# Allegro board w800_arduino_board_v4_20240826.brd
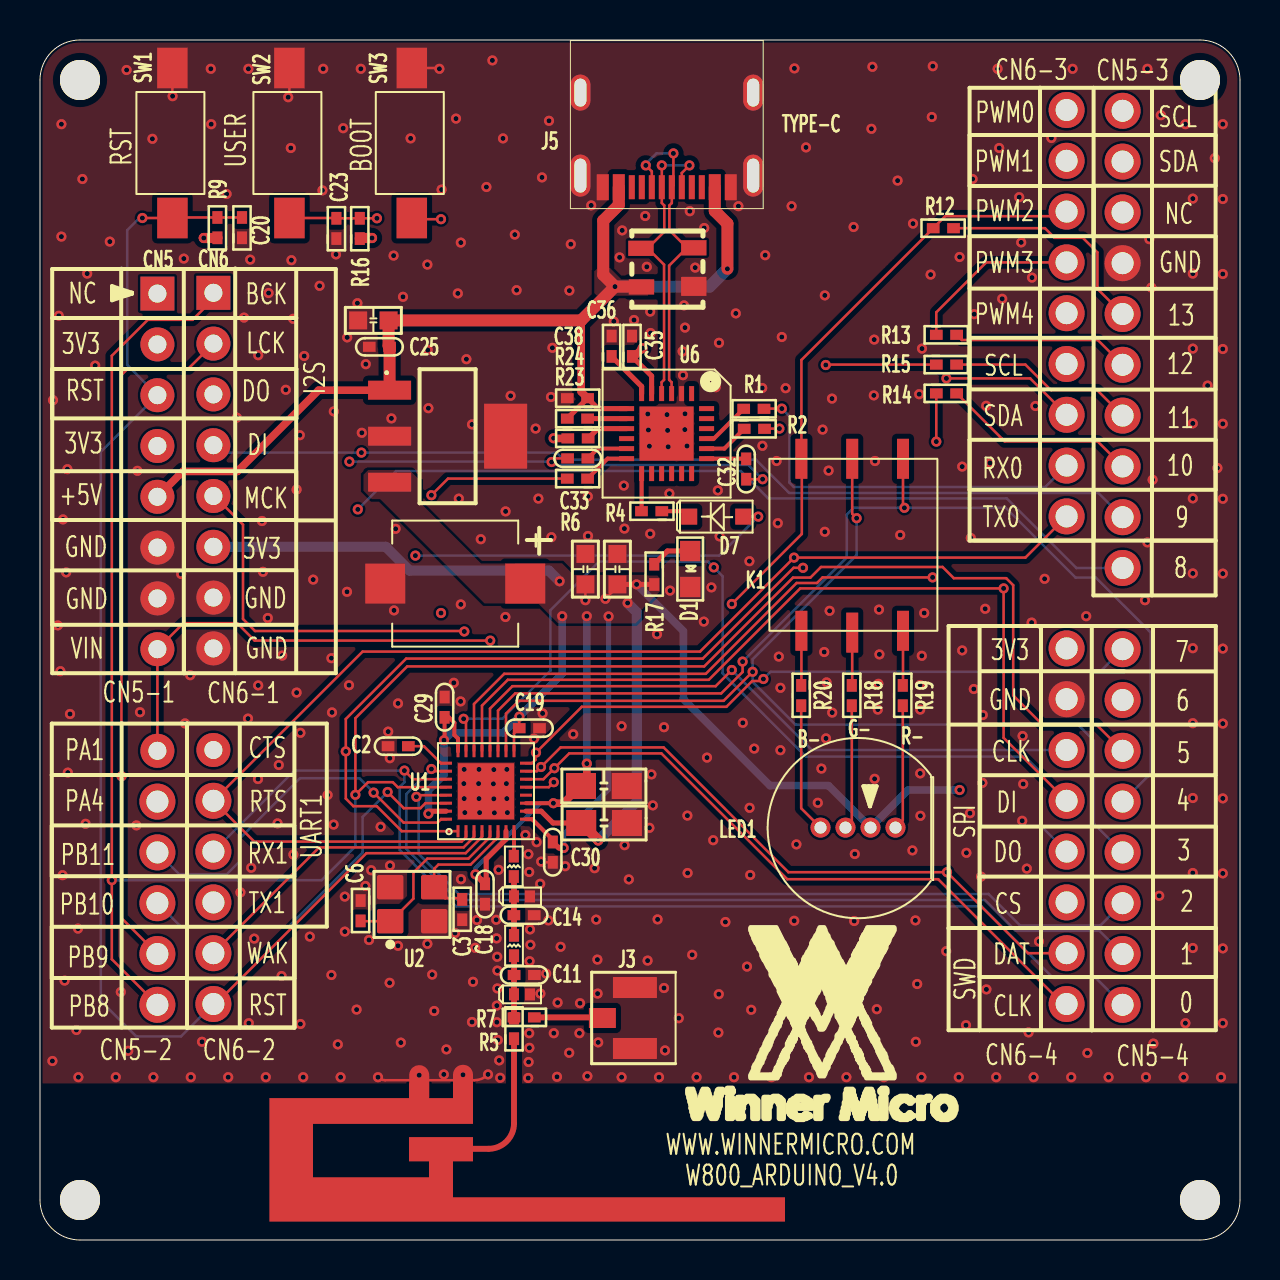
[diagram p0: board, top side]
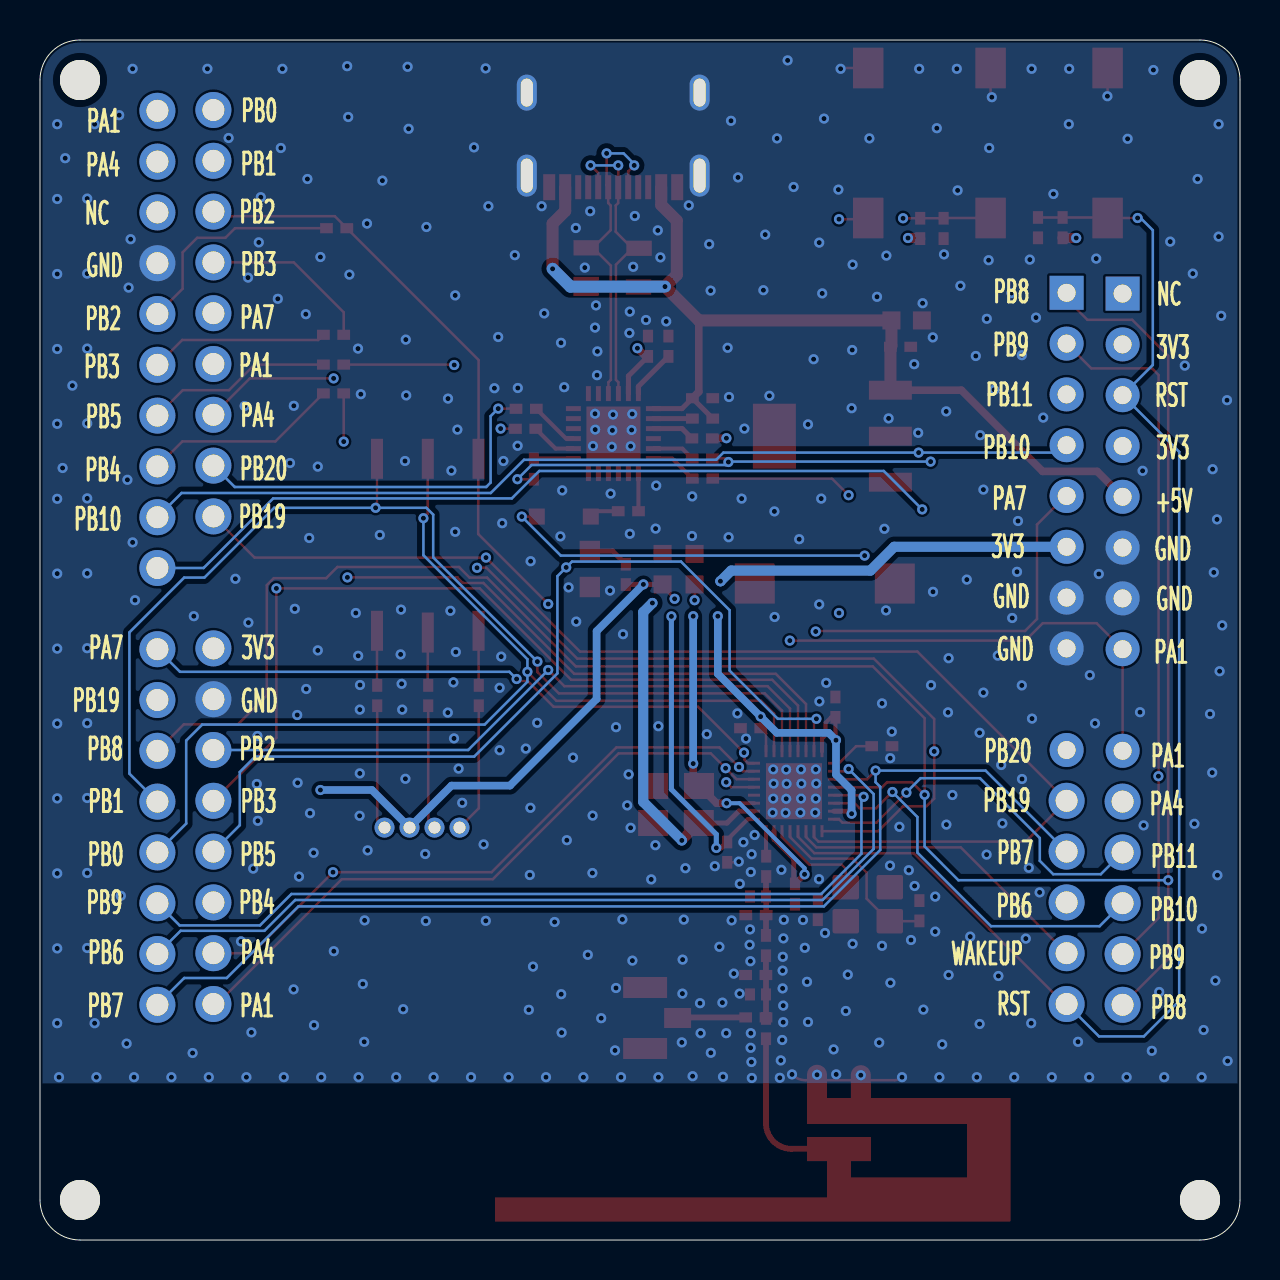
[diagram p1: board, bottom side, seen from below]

Outline 60 x 60 mm; copper layers: TOP, GND1, GND2, BOTTOM. Coordinates in mm from the lower left corner of the outline.
Outline path: 0,58 0,2 arc(0.59,0.59) 2,0 58,0 arc(59.41,0.59) 60,2 60,58 arc(59.41,59.41) 58,60 2,60 arc(0.59,59.41) 0,58

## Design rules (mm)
constraint set DEFAULT: min track width 0.127
net group D: nets DN DP

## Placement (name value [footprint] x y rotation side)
C2  4.7uF  [C0402]  18.42 24.69 180 top
C3  15pF  [R0402]  21.11 17.03 270 top
C6  15pF  [R0402]  16.03 16.97 270 top
C11  2pF  [C0402]  24.72 13.25 180 top
C14  1.5pF  [C0402]  24.71 16.24 180 top
C17  47uF  [C0805]  28.2 20.85 0 top
C18  1uF  [C0402]  22.25 17.81 270 top
C19  1uF  [C0402]  23.96 25.59 0 top
C20  1uF  [R0402]  10.1 50.11 90 top
C23  NC  [R0402]  14.82 50.07 90 top
C24  10uF  [C0603]  16.67 45.98 180 top
C25  1uF  [C0402]  17.48 44.66 180 top
C26  10uF  [C0603]  27.27 33.54 90 top
C27  10uF  [C0603]  28.87 33.54 90 top
C28  330uF  [CAPE-6DX13L]  20.76 32.82 180 top
C29  1uF  [C0402]  20.23 26.13 90 top
C30  10nF  [C0402]  25.64 19.9 270 top
C31  8.2pF  [L0402]  23.69 18.68 270 top
C32  4.7uF  [C0402]  35.31 38.04 90 top
C33  4.7uF  [C0402]  26.38 39.08 0 top
C35  1uF  [R0402]  29.6 44.18 90 top
C36  0.1uF  [R0402]  28.58 44.18 90 top
C38  1uF  [R0402]  27.38 42.09 180 top
C39  47uF  [C0805]  28.19 22.7 0 top
CN5  DIP8  [ARDUINO_HDRM2]  5.87 27 0 top
CN6  DIP8  [ARDUINO_HDRMDIP]  5.87 27.04 0 top
D1  LED  [LED0603]  32.51 33.55 270 top
D2  WM0310001  [TVS0402]  24.1 12.28 0 top
D3  WM0310001  [TVS0402]  24.1 17.18 0 top
D7  1N5819WS  [SOD-323]  32.46 36.17 0 top
J3  IPX  [TC35]  28.98 11.1 0 top
J4  ANT  [IFA_TI1]  24.36 4.38 180 top
J5  -  [TYPE-C]  31.34 59.97 180 top
K1  EM-03KP  [SWITCH3_2]  38.07 39.06 0 top
L2  1.5nH  [L0402]  23.7 14.72 270 top
LED1  8MM RGB LED  [RGB_LED]  40.9 20.62 180 top
NOREF  -  [unnamed]  2 58 0 top
NOREF#2  -  [unnamed]  58 2 0 top
NOREF#3  -  [unnamed]  58 58 0 top
NOREF#4  -  [unnamed]  2 2 0 top
R1  33R  [R0402]  36.2 41.56 180 top
R2  33R  [R0402]  35.21 40.56 0 top
R4  33R  [R0402]  31.09 36.44 180 top
R5  8.2pF  [R0402]  23.7 10.06 90 top
R6  33R  [R0402]  27.38 38.07 180 top
R7  NC  [R0402]  24.72 11.13 180 top
R9  10K  [R0402]  8.87 50.11 90 top
R12  33R  [R0402]  44.66 50.59 0 top
R13  33R  [R0402]  44.81 45.26 0 top
R14  33R  [R0402]  44.81 42.33 0 top
R15  33R  [R0402]  44.81 43.77 0 top
R16  10K  [R0402]  15.99 50.07 90 top
R17  1.5K  [R0402]  30.71 33.79 270 top
R18  100R  [R0402]  40.59 27.73 270 top
R19  100R  [R0402]  43.14 27.73 270 top
R20  100R  [R0402]  38.06 27.73 270 top
R23  NC  [R0402]  26.39 40.08 0 top
R24  0R  [R0402]  27.38 41.07 180 top
SW1  K2-1107ST-A4SW-06  [SW4]  6.62 51.1 90 top
SW2  K2-1107ST-A4SW-06  [SW4]  12.47 51.1 90 top
SW3  K2-1107ST-A4SW-06  [SW4]  18.59 51.1 90 top
U1  W800_32pin  [W800-QFN32]  22.3 22.44 90 top
U2  XTAL_40MHz  [OSCCC250X320X110]  18.8 16.93 90 top
U4  AP7361-33E-13  [SOT-223]  20.38 40.19 270 top
U6  CH342F  [QFN24_4MMX4MM]  31.33 40.32 270 top
U7  SP0503BAHTG  [SOT143_2]  31.37 48.54 90 top

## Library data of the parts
C2 C3 C6 C11 C14 C17-C20 C23-C27 C29 C30 C32 C33 C35 C36 C38 C39 = CAP NP
C28 = C_0: room: PWR
C31 L2 = INDUCTOR
CN5 = CON8_5
CN6 = CON8_9
D1 = LED_0
D2 D3 = TRANZORB_0
D7 = LED_1
J3 J4 = TC35
J5 = TYPE-C_2
K1 = SWITCH_2
LED1 = RGB_0
R1 R2 R4 R6 R12-R15 R17-R20 R23 R24 = R
R5 R7 R9 R16 = R: room: FPGA_BANK3_4_CLK
SW1-SW3 = SW PUSHBUTTON_0
U1 = W600_10
U2 = OSC44M_0
U4 = AMS117_0
U6 = CP2105_0
U7 = SP0503BAHTG_0

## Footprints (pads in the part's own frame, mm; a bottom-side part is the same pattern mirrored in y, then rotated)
ARDUINO_HDRM2
  rect 1.7x1.7 hole 0.9: 1(0,20.32)
  round 1.7 hole 0.9: 2(0,17.78) 3(0,15.24) 4(0,12.7) 5(0,10.16) 6(0,7.62) 7(0,5.08) 8(0,2.54) 9(0,-2.54)
  round 1.8 hole 1.1: 10(0,-5.08) 11(0,-7.62) 12(0,-10.16) 13(0,-12.7) 14(0,-15.24) 15(48.26,-15.24) 16(48.26,-12.7) 17(48.26,-10.16) 18(48.26,-7.62) 19(48.26,-5.08) 20(48.26,-2.54) 21(48.26,0) 22(48.26,2.54) 23(48.26,6.6) 24(48.26,9.14) 25(48.26,11.68) 26(48.26,14.22) 27(48.26,16.76) 28(48.26,19.3) 29(48.26,21.84) 30(48.26,24.38) 31(48.26,26.92) 32(48.26,29.46)
ARDUINO_HDRMDIP
  rect 1.7x1.7 hole 0.9: 1(2.8,20.32)
  round 1.7 hole 0.9: 2(2.8,17.78) 3(2.8,15.24) 4(2.8,12.7) 5(2.8,10.16) 6(2.8,7.62) 7(2.8,5.08) 8(2.8,2.54) 9(2.8,-2.54)
  round 1.8 hole 1.1: 10(2.8,-5.08) 11(2.8,-7.62) 12(2.8,-10.16) 13(2.8,-12.7) 14(2.8,-15.24) 15(45.46,-15.24) 16(45.46,-12.7) 17(45.46,-10.16) 18(45.46,-7.62) 19(45.46,-5.08) 20(45.46,-2.54) 21(45.46,0) 22(45.46,2.54) 24(45.46,9.14) 25(45.46,11.68) 26(45.46,14.22) 27(45.46,16.76) 28(45.46,19.3) 29(45.46,21.84) 30(45.46,24.38) 31(45.46,26.92) 32(45.46,29.46)
C0402
  rect 0.635x0.508 smd: 1(0,0) 2(1.016,0)
C0603
  rect 0.9x0.9 smd: 1(-0.762,0) 2(0.762,0)
C0805
  rect 1.5x1.3 smd: 1(-1.143,0) 2(1.143,0)
CAPE-6DX13L
  rect 2x2 smd: 1(-3.5,0) 2(3.5,0)
IFA_TI1
  rect 0.508x0.432 smd: 1(4.14,-0.18) 2(3.21,-2.8) 3(5.4,-2.78)
L0402
  rect 0.635x0.508 smd: 1(-0.508,0) 2(0.508,0)
LED0603
  rect 1.016x1.016 smd: 1(-0.9,0) 2(0.9,0)
OSCCC250X320X110
  custom 0.305x0.305 smd: 1(-0.99,1.29) 2(-0.99,-0.91) 3(0.71,-0.91) 4(0.71,1.29)
QFN24_4MMX4MM
  rect 0.75x0.25 smd: 1(-2,1.25) 2(-2,0.75) 3(-2,0.25) 4(-2,-0.25) 5(-2,-0.75) 6(-2,-1.25) 13(2,-1.25) 14(2,-0.75) 15(2,-0.25) 16(2,0.25) 17(2,0.75) 18(2,1.25)
  rect 0.25x0.75 smd: 7(-1.25,-2) 8(-0.75,-2) 9(-0.25,-2) 10(0.25,-2) 11(0.75,-2) 12(1.25,-2) 19(1.25,2) 20(0.75,2) 21(0.25,2) 22(-0.25,2) 23(-0.75,2) 24(-1.25,2)
  rect 2.7x2.7 smd: 25(0,0)
R0402
  rect 0.635x0.508 smd: 1(0,0) 2(1.016,0)
RGB_LED
  round 1 hole 0.6: 1(-1.875,0) 2(-0.625,0) 3(0.625,0) 4(1.875,0)
SOD-323
  rect 0.8x0.8 smd: 1(0,0) 2(2.7,0)
SOT143_2
  rect 0.95x1.27 smd: 1(-0.864,-1.321)
  rect 0.762x1.27 smd: 2(1.067,-1.321) 3(1.041,1.321) 4(-0.889,1.295)
SOT-223
  rect 0.95x2.15 smd: 1(-2.3,-2.9) 2(0,-2.9) 3(2.3,-2.9)
  rect 3.25x2.15 smd: 4(0,2.9)
SW4
  rect 2.032x1.524 smd: 1(0,0) 2(7.5,0)
SWITCH3_2
  rect 0.6x2 smd: 1(0,0) 2(2.54,0) 3(5.08,0) 4(5.08,-8.6) 5(2.54,-8.69) 6(0,-8.6)
TC35
  rect 1.35x1 smd: 1(-0.864,0)
  rect 2.2x1.05 smd: 2(0.762,-1.524) 3(0.762,1.524)
TVS0402
  rect 0.5x0.6 smd: 1(-0.4,0) 2(0.4,0)
TYPE-C
  rect 0.6x1.3 smd: 1(-3.2,7.33) 2(-2.4,7.33) 11(2.4,7.33) 12(3.2,7.33)
  rect 0.3x1.2 smd: 3(-1.75,7.33) 4(-1.25,7.33) 5(-0.75,7.33) 6(-0.25,7.33) 7(0.25,7.33) 8(0.75,7.33) 9(1.25,7.33) 10(1.75,7.33)
  oval 1x2.1 hole 0.6x1.7: 13(4.32,6.75) 14(-4.32,6.75)
  oval 1x1.8 hole 0.6x1.4: 15(-4.32,2.6) 16(4.32,2.6)
unnamed
  round 2 hole 2.3 unplated: (0,0)
W800-QFN32
  rect 0.6x0.15 smd: 1(-2,1.4) 2(-2,1) 3(-2,0.6) 4(-2,0.2) 5(-2,-0.2) 6(-2,-0.6) 7(-2,-1) 8(-2,-1.4) 17(2,-1.4) 18(2,-1) 19(2,-0.6) 20(2,-0.2) 21(2,0.2) 22(2,0.6) 23(2,1) 24(2,1.4)
  rect 0.15x0.6 smd: 9(-1.4,-2) 10(-1,-2) 11(-0.6,-2) 12(-0.2,-2) 13(0.2,-2) 14(0.6,-2) 15(1,-2) 16(1.4,-2) 25(1.4,2) 26(1,2) 27(0.6,2) 28(0.2,2) 29(-0.2,2) 30(-0.6,2) 31(-1,2) 32(-1.4,2)
  rect 2.8x2.8 smd: 33(0,0)

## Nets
+5V: C24.1 C25.1 C38.1 CN5.5 J5.2(VBUS#2) J5.11 R24.2 U4.1 U6.7 U7.4
GND: C2.2 C3.2 C6.1 C11.1 C14.1 C17.2 C18.2 C19.2 C20.1 C23.1 C24.2 C25.2 C26.2 C27.2 C28.2 C29.2 C30.2 C35.2 C36.2 C38.2 C39.2 CN5.6 CN5.7 CN5.29 CN6.7 CN6.8 CN6.21 D1.2 D2.2(CATHODE) D3.2(CATHODE) J3.2 J3.3 J4.2 J4.3 J5.1 J5.12 J5.13 J5.14 J5.15 J5.16 SW1.2 SW2.2 SW3.2 U1.33 U2.2 U2.4 U4.2 U4.4 U6.2 U6.25 U7.1
VCC_33: C17.1 C18.1 C19.1 C26.1 C27.1 C28.1 C29.1 C30.1 C35.1 C39.1 CN5.2 CN5.4 CN6.6 CN6.22 LED1.2 R9.1 R16.1 R17.2 R23.1 U1.7 U1.9 U1.10 U1.11 U1.17 U1.24 U1.31 U4.3(VOUT) U6.5(VIO)
ANT: J4.1(IN) R5.1
DN: J5.5 J5.7 U6.4 U7.3
DP: J5.6 J5.8 U6.3 U7.2
PA0: SW3.1 U1.13
PA1: CN5.8 CN5.9 CN5.32 CN6.15 CN6.27 U1.14
PA4: CN5.10 CN5.31 CN6.16 CN6.26 U1.15
PA7: CN5.22 CN6.5 CN6.28 U1.16
PB0: CN5.18 CN6.32 K1.2 U1.18
PB1: CN5.19 CN6.31 K1.3 U1.19
PB2: CN6.20 CN6.30 K1.1 R12.1 U1.20
PB3: CN6.19 CN6.29 R13.1 U1.21
PB4: CN6.17 R14.1 U1.22
PB5: CN6.18 R15.1 U1.23
PB6: CN5.16 CN6.12 R6.2 U1.26
PB7: C23.2 CN5.15 CN6.11 D7.2 R16.2 SW2.1 U1.27
PB8: CN5.14 CN5.20 CN6.1 U1.28
PB9: CN5.13 CN5.17 CN6.2 U1.29
PB10: CN5.12 CN5.24 CN6.4 U1.30
PB11: CN5.11 CN5.23 CN6.3 U1.32
PB19: CN5.21 CN6.10 CN6.24 R2.2 U1.2
PB20: CN6.9 CN6.25 R1.1 U1.1
RST_N: C20.2 C32.1 C33.1 CN5.3 CN6.14 R9.2 SW1.1 U1.4
WAKEUP: CN6.13 U1.3
XTAL_IN: C3.1 U1.6 U2.3(OUT2)
XTAL_OUT: C6.2 U1.5(XO) U2.1
N16680375: D1.1 R17.1
N16684582: R4.2 U6.13
N16684586: R6.1 U6.12
N16727459: K1.5 R18.1
N16727471: LED1.3 R18.2
N16730113: K1.4 R19.1
N16730133: K1.6 R20.1
N16730206: LED1.4 R20.2
N16730210: LED1.1(R-) R19.2
N16735482: C33.2 U6.11
N16736464: C32.2 U6.19
N16746225: C11.2 D2.1 L2.2 R5.2 R7.2
N16746337: C2.1 U1.25
N16746437: C14.2 C31.2 D3.1 L2.1
N16750371: J3.1(IN) R7.1
N16770024: CN5.28 R12.2
N16770030: CN5.27 R13.2
N16770036: CN5.26 R15.2
N16770042: CN5.25 R14.2
N16796539: C31.1 U1.8
N16801010: R1.2 U6.21
N16801016: R2.1 U6.20
N16801188: C36.1 U6.6
N16801254: R23.2 U6.9
N16808784: R24.1 U6.8
N166846780: D7.1(CATHODE) R4.1

Pads without a net: CN5 1 30; J5 3 4 9 10; U1 12; U6 1 10 14 15 16 17 18 22 23 24

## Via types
v1: diameter 0.508, hole 0.254, TOP to BOTTOM, 517 vias

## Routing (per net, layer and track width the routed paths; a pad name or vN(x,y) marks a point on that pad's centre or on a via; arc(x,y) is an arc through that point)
+5V: length 54.2
  TOP w0.254: U6.7 27.9,41.57 C38.1 26.36,41.07 R24.2
  TOP w0.381: 27.06,45.98 27.06,42.41 C38.1 ; U4.1 13.93,42.49 9.87,38.43 7.14,38.43 CN5.5
  TOP w0.6: v1(28.75,47.67) 30.06,47.67 U7.4 ; v1(28.75,47.67) 28.16,48.26 28.16,50.97 28.94,51.75 J5.11 ; v1(28.75,47.67) 27.06,45.98 C24.1 17.43,44.71 C25.1 U4.1 ; J5.2 33.74,51.45 34.37,50.82 v1(34.37,48.56)
  BOTTOM w0.6: v1(34.37,48.56) 33.48,47.67 v1(28.75,47.67)
GND: length 12.7
  TOP w0.127: v1(12.41,57.14) 12.47,57.2 SW2.2 ; C30.2 25.1,18.88 v1(25.06,18.92) ; v1(6.63,57.19) 6.62,57.2 SW1.2 ; v1(22.4,8.28) 22.39,8.27 arc(22.08,8.06) 21.72,7.99 17.26,7.99 arc(17.07,8.03) v1(16.9,8.14) ; v1(19.97,58.56) 19.93,58.6 SW3.2 ; v1(20.19,8.28) 20.2,8.27
  TOP w1: J4.2 v1(21.15,8.26) ; J4.3 v1(18.96,8.24)
  vias: v1(0.65,41.99) v1(0.62,8.95) v1(0.94,46.21) v1(0.89,30.73) v1(1.02,28.44) v1(1.07,55.79) v1(1.07,50.17) v1(1.15,36.03) v1(1.13,18.24) v1(1.23,12.97) v1(1.31,33.38) v1(1.37,38.54) v1(1.39,23.37) v1(1.5,26.3) v1(1.82,10.5) v1(1.9,15.57) v1(1.92,8.14) v1(2.12,53.05) v1(2.28,20.81) v1(2.36,48.32) v1(2.76,43.72) v1(3.49,49.92) v1(3.79,8.14) v1(4.04,12.4) v1(4.33,58.5) v1(4.41,9.46) v1(4.82,20.73) v1(4.87,38.46) v1(5,26.39) v1(5.62,55.06) v1(5.67,8.14) v1(7.06,33.3) v1(7.19,49.07) v1(7.25,25.83) v1(7.51,28.24) v1(7.54,8.14) v1(8.1,9.91) v1(8.54,58.56) v1(8.56,55.79) v1(9.33,52.3) v1(9.41,8.14) v1(9.84,41.12) v1(10.02,17.38) v1(10.2,46.12) v1(10.42,58.56) v1(10.4,26.07) v1(10.44,10.84) v1(10.51,49.02) v1(10.56,18.61) v1(10.71,15.07) v1(10.91,44.24) v1(10.91,27.73) v1(10.9,23.05) v1(11.1,35.95) v1(11.15,33.41) v1(11.29,8.14) v1(11.43,47.35) v1(11.39,31.1) v1(11.94,23.75) v1(11.88,20.83) v1(12.11,29.22) v1(12.08,13.2) v1(12.29,42.51) v1(12.54,54.6) v1(12.57,48.99) v1(12.66,46.06) v1(12.67,19.27) v1(12.83,37.52) v1(12.83,27.37) v1(12.99,40.24) v1(13.02,25.36) v1(13.02,10.8) v1(13.21,44.2) v1(13.16,8.14) v1(13.49,15.17) v1(13.66,33.02) v1(13.98,47.71) v1(14.12,52.48) v1(14.16,58.56) v1(14.38,22.25) v1(14.57,29.09) v1(14.6,26.38) v1(14.57,13.25) v1(14.69,41.43) v1(14.68,20.77) v1(14.8,49.28) v1(14.89,9.78) v1(15.03,8.14) v1(15.16,55.59) v1(15.24,17.17) v1(15.24,15.42) v1(15.35,32.41) v1(15.36,45.13) v1(15.45,27.74) v1(15.83,11.52) v1(15.87,46.84) v1(16.04,58.56) v1(16.09,40.36) v1(16.29,43.79) v1(16.27,17.7) v1(16.45,15) v1(16.56,18.49) v1(17.03,20.66) v1(17.41,25.42) v1(17.49,24.09) v1(17.5,18.72) v1(17.48,12.86) v1(17.57,41.08) v1(17.68,49.22) v1(17.7,31.48) v1(17.78,35.56) v1(17.9,26.83) v1(17.9,14.71) v1(18.04,9.87) v1(18.15,47.16) v1(18.53,55.08) v1(19.37,48.77) v1(19.39,44.5) v1(19.42,41.59) v1(19.37,14.81) v1(19.61,13.27) v1(19.71,11.45) v1(20.08,52.52) v1(20.32,9.53) v1(20.69,27.86) v1(20.8,56.07) v1(20.75,15.35) v1(20.89,47.33) v1(20.94,37.07) v1(21.04,49.87) v1(21.04,31.78) v1(21.03,26.93) v1(21.05,18.04) v1(21.21,23.53) v1(21.19,22.82) v1(21.21,22.07) v1(21.24,21.37) v1(21.32,44.04) v1(21.6,40.78) v1(21.65,12.91) v1(21.6,10.9) v1(21.76,14.61) v1(21.95,23.53) v1(21.93,22.82) v1(21.95,22.07) v1(21.85,16) v1(22.04,35.04) v1(21.98,21.37) v1(22.32,52.65) v1(22.62,58.98) v1(22.69,23.52) v1(22.67,22.81) v1(22.69,22.06) v1(22.72,21.36) v1(22.81,16.01) v1(22.83,15.08) v1(22.84,11.72) v1(22.84,10.89) v1(22.93,18.51) v1(22.86,14.16) v1(22.87,13.47) v1(22.87,12.58) v1(22.89,10) v1(22.96,8.98) v1(23.01,8.11) v1(23.15,55.08) v1(23.28,36.43) v1(23.27,31.15) v1(23.34,23.53) v1(23.32,22.82) v1(23.34,22.07) v1(23.37,21.37) v1(23.53,42.21) v1(23.74,50.27) v1(23.83,47.49) v1(24.27,20.25) v1(24.42,19.29) v1(24.43,8.9) v1(24.41,8.1) v1(24.46,18.4) v1(24.5,15.53) v1(24.52,14.76) v1(24.48,13.94) v1(24.46,10.34) v1(24.47,9.61) v1(24.7,25.07) v1(24.78,40.57) v1(24.83,19.89) v1(24.92,37.07) v1(25.01,17.81) v1(25.02,12.32) v1(25.1,53.13) v1(25.13,26.33) v1(25.31,13.32) v1(25.45,55.96) v1(25.42,15.98) v1(25.62,44.61) v1(25.55,42.15) v1(25.57,35.14) v1(25.69,10.34) v1(25.88,11.87) v1(25.85,8.16) v1(26.03,14.66) v1(26.26,18.69) v1(26.54,49.79) v1(26.47,47.47) v1(26.46,9.36) v1(26.66,25.29) v1(27,11.84) v1(26.97,10.34) v1(27.39,37.18) v1(27.4,35.2) v1(27.37,8.19) v1(27.56,51.73) v1(27.73,18.59) v1(27.81,16.02) v1(27.87,14.02) v1(27.88,12.32) v1(27.91,9.88) v1(28.69,45.93) v1(28.98,49.13) v1(29.11,50.48) v1(29.08,25.69) v1(29.08,8.14) v1(29.19,37.72) v1(29.22,35.57) v1(29.23,19.74) v1(29.44,18.03) v1(29.7,46) v1(30.26,51.2) v1(30.34,48.66) v1(30.39,41.3) v1(30.42,40.5) v1(30.38,13.97) v1(30.51,46.42) v1(30.53,45.35) v1(30.47,39.69) v1(30.51,35.31) v1(30.47,20.61) v1(30.57,23.28) v1(30.64,21.73) v1(30.85,30.29) v1(30.88,16.03) v1(30.95,8.14) v1(31.2,25.64) v1(31.2,12.6) v1(31.25,9.48) v1(31.35,41.27) v1(31.38,40.48) v1(31.41,39.66) v1(31.47,37.32) v1(31.5,32.47) v1(31.94,11.09) v1(32.13,44.43) v1(32.15,43.24) v1(32.2,46.73) v1(32.25,45.62) v1(32.25,41.31) v1(32.24,40.52) v1(32.35,39.7) v1(32.37,21.22) v1(32.38,18.35) v1(32.49,51.44) v1(32.61,14.26) v1(32.76,48.62) v1(32.83,8.14) v1(33.21,50.6) v1(33.19,30.92) v1(33.35,24.12) v1(33.57,32.63) v1(33.66,19.99) v1(33.79,42.64) v1(33.95,44.86) v1(33.89,37.48) v1(33.94,12.29) v1(33.92,10.37) v1(33.98,35.18) v1(34.27,15.9) v1(34.7,8.14) v1(34.79,46.33) v1(34.92,51.69) v1(35.14,25.86) v1(35.35,13.67) v1(35.47,33.94) v1(35.48,21.61) v1(35.51,18.25) v1(35.56,11.51) v1(35.71,24.57) v1(36.11,42.6) v1(36.12,39.71) v1(36.26,49.24) v1(36.57,8.14) v1(36.83,38.95) v1(36.89,35.84) v1(36.94,29.17) v1(37.02,27.61) v1(37.02,24.49) v1(37.09,45.15) v1(37.28,42.59) v1(37.58,51.69) v1(37.72,58.58) v1(37.71,15.96) v1(37.82,19.78) v1(38.3,54.63) v1(38.45,8.14) v1(38.89,21.86) v1(39.13,40.52) v1(39.07,23.57) v1(39.24,47.23) v1(39.24,35.41) v1(39.21,29.4) v1(39.33,27.88) v1(39.3,25.08) v1(39.43,38.47) v1(39.48,31.46) v1(39.6,42.07) v1(39.61,26.37) v1(40.32,8.14) v1(40.68,50.65) v1(40.74,19.3) v1(40.71,15.95) v1(41.62,58.66) v1(41.57,55.56) v1(41.71,45.02) v1(41.69,42.23) v1(41.73,23.06) v1(41.75,38.95) v1(41.84,11.54) v1(41.92,27.81) v1(41.89,26.52) v1(41.95,31.52) v1(41.97,29.28) v1(42.19,8.14) v1(42.88,52.97) v1(43.01,35.25) v1(43.65,50.82) v1(43.62,19.48) v1(43.77,15.98) v1(43.79,9.91) v1(43.86,12.8) v1(43.96,42.29) v1(44,27.75) v1(44.01,26.52) v1(44.01,23.33) v1(44.02,21.21) v1(44.1,44.57) v1(44.09,29.21) v1(44.07,8.14) v1(44.21,31.35) v1(44.53,48.27) v1(44.64,58.69) v1(44.59,56.15) v1(45.31,14.44) v1(45.94,8.14) v1(45.98,49.15) v1(46.11,38.67) v1(46.11,29.48) v1(46.32,19.36) v1(46.3,10.74) v1(46.54,35.1) v1(46.5,21.34) v1(46.63,53.05) v1(46.71,46.29) v1(46.69,27.55) v1(47.05,18.17) v1(47.14,26.25) v1(47.12,22.86) v1(47.31,41.71) v1(47.26,31.56) v1(47.32,12.53) v1(47.5,38.85) v1(47.81,8.14) v1(47.88,58.56) v1(47.96,54.6) v1(48.11,47.06) v1(48.96,52.14) v1(49.06,49.88) v1(49.13,25.2) v1(49.11,20.96) v1(49.16,22.8) v1(49.34,18.57) v1(49.43,10.38) v1(49.6,48.12) v1(49.58,30.87) v1(49.68,8.14) v1(49.77,41.7) v1(49.95,14.93) v1(50.23,33.06) v1(50.57,55.1) v1(51.63,58.56) v1(51.56,8.14) v1(52.31,31.19) v1(52.37,9.35) v1(53.43,8.14) v1(55.25,31.99) v1(55.3,8.14) v1(55.37,58.56) v1(55.37,34.88) v1(55.47,50.04) v1(55.57,47.62) v1(55.63,38.01) v1(55.67,9.82) v1(56.04,56.24) v1(55.96,17.21) v1(57.18,8.14) v1(57.27,55.79) v1(57.27,10.84) v1(57.64,52.07) v1(57.64,48.32) v1(57.64,44.57) v1(57.64,40.83) v1(57.64,37.08) v1(57.64,33.33) v1(57.64,29.59) v1(57.64,25.84) v1(57.64,22.1) v1(57.64,18.35) v1(57.64,14.6) v1(58.38,42.72) v1(58.74,54.09) v1(58.87,38.6) v1(59.05,8.14) v1(59.14,55.79) v1(59.14,52.05) v1(59.14,48.3) v1(59.14,44.55) v1(59.14,40.81) v1(59.14,37.06) v1(59.14,33.32) v1(59.14,29.57) v1(59.14,25.82) v1(59.14,22.08) v1(59.14,18.33) v1(59.14,14.58) v1(59.14,10.84)
VCC_33: length 187.7
  TOP w0.127: C27.1 28.87,32.66 v1(28.27,32.06) ; v1(23.97,26.17) 23.96,26.16 C19.1 23.7,25.33 U1.17 ; C26.1 v1(27.27,31.99)
  TOP w0.2: U1.24 20.9,25.07 20.72,25.25 20.72,25.86 20.45,26.13 C29.1 20.23,25.02 v1(20.2,24.99)
  TOP w0.203: U1.9 24.61,21.04 25.64,20.01 C30.1 ; U1.11 v1(25.67,21.84)
  TOP w0.254: U6.5 30.58,43.2 C35.1 ; R17.2 30.7,32.78 v1(29.83,32.78) C27.1 ; U1.31 19.52,21.44 19.42,21.34 v1(19.42,21.32) ; C18.1 22.31,17.87 22.31,19.05 23.3,20.04 U1.7 ; C17.1 25.65,20.85 25.06,21.44 U1.10 ; C30.1 25.93,19.6 v1(26.18,19.6)
  TOP w0.3: C18.1 v1(21.77,18.28)
  TOP w0.381: v1(30.13,44.59) 29.72,44.18 C35.1 ; v1(25.68,40.09) 25.69,40.08 R23.1 ; v1(27.34,23.82) 27.34,22.99 C39.1 27.03,22.7 26.17,21.84 v1(25.67,21.84)
  TOP w0.508: v1(8.19,50.1) 8.86,50.1 R9.1 ; v1(16.6,50.1) 16.02,50.1 R16.1 ; C17.1 27.91,20 v1(27.91,19.98)
  GND2 w0.381: v1(25.68,40.09) 26.53,39.24 26.53,32.73 v1(27.27,31.99) ; v1(28.27,32.06) 28.27,42.73 v1(30.13,44.59) ; v1(45.98,22.5) 45.98,27.87 47.69,29.58 CN6.22
  GND2 w0.508: v1(16.6,50.1) v1(8.19,50.1) 5.48,50.1 4.13,48.75 4.13,46.52 CN5.2 4.29,43.2 4.29,41.28 CN5.4 7.32,38.25 7.32,36.01 CN6.6
  BOTTOM w0.203: v1(25.67,21.84) 25.02,21.84 21.77,18.59 v1(21.77,18.28)
  BOTTOM w0.254: v1(28.43,31.18) 28.43,22.53 26.18,20.28 v1(26.18,19.6)
  BOTTOM w0.381: v1(27.34,31.19) v1(27.34,23.82) ; v1(29.83,32.78) 32.17,30.44 32.17,27.05 36.5,22.72 39.42,22.72 LED1.2 43.41,22.5 v1(45.98,22.5) ; v1(26.11,31.19) 26.11,28.31 v1(23.97,26.17) 23.16,25.36 20.57,25.36 v1(20.2,24.99) 20.2,23.27 19.42,22.49 v1(19.42,21.32)
  BOTTOM w0.508: v1(25.98,32.94) 25.97,32.94 25.44,33.47 18.48,33.47 17.29,34.66 CN6.6 ; v1(29.38,31.85) 29.84,31.39 29.84,21.91 v1(27.91,19.98)
ANT: length 8.4
  TOP w0.293: J4.1 22.43,4.56 arc(23.33,4.93) 23.7,5.83 R5.1
DN: length 15.2
  TOP w0.127: U7.3 30.39,49.59 ; 30.39,49.59 31.21,50.41 31.21,51.73 31.09,51.85 J5.7 v1(31.09,53.73) ; 30.39,49.59 31.2,48.77 31.2,43.01 31.08,42.89 U6.4 ; J5.5 32.09,53.35 v1(32.47,53.73)
  BOTTOM w0.127: v1(32.47,53.73) v1(31.09,53.73)
DP: length 16.1
  TOP w0.127: v1(30.29,53.73) 30.59,53.43 J5.8 ; U6.3 31.58,42.89 31.46,43.01 31.46,48.72 32.35,49.61 ; 32.35,49.61 31.47,50.49 31.47,51.73 31.59,51.85 J5.6 31.67,52.72 v1(31.67,54.33) ; 32.35,49.61 U7.2
  BOTTOM w0.127: v1(30.29,53.73) 30.29,53.8 30.82,54.33 v1(31.67,54.33)
PA0: length 36.2
  TOP w0.127: SW3.1 18.65,51.04 v1(20.05,51.04) ; U1.13 25.44,22.64 v1(25.69,22.89)
  GND2 w0.127: v1(25.69,22.89) 26.19,23.39 26.19,29.1 24.87,30.42 21.86,30.42 21.41,30.87 20.53,30.87 v1(20.05,31.35) v1(20.05,51.04)
PA1: length 121.2
  TOP w0.127: CN5.9 CN5.8 7.17,30.84 9.86,30.84 10.73,29.97 v1(22.51,29.97) ; U1.14 25.17,23.04 v1(25.72,23.59) 26.46,24.33 31.07,24.33 37.36,18.04 44.91,18.04 51.15,11.8 CN6.15
  GND2 w0.127: CN6.27 52.62,42.51 55.79,42.51 56.95,41.35 ; v1(22.51,29.97) 24.78,29.97 25.91,28.84 25.91,23.78 v1(25.72,23.59) ; 56.95,41.35 56.95,14.87 55.15,13.07 52.6,13.07 CN6.15 ; 56.95,41.35 56.95,54.27 54.76,56.46 CN5.32
PA4: length 108.8
  TOP w0.127: CN6.16 49.4,14.34 v1(45.35,18.39) 37.42,18.39 31.18,24.63 26.03,24.63 v1(25.05,23.65) 24.84,23.44 U1.15 ; CN6.26 49.51,43.08 v1(45.32,43.08)
  GND2 w0.127: CN5.31 52.95,52.74 48.52,52.74 45.32,49.54 v1(45.32,43.08) 45.32,18.42 v1(45.35,18.39) ; CN5.10 7.26,20.53 7.26,16.42 7.98,15.7 11.53,15.7 15.44,19.6 22.66,19.6 24.83,21.78 24.83,23.34 25.05,23.56 v1(25.05,23.65)
PA7: length 80.5
  TOP w0.127: U1.16 24.6,23.84 24.77,24.01 24.77,24.34 v1(24.8,24.37) 27.09,26.66 34.32,26.66 35.61,27.95 36.07,27.95 v1(36.17,28.05) ; CN6.5 8.72,37.2 10.15,35.77 10.15,31.05 10.75,30.45 21.19,30.45 v1(21.21,30.43)
  GND2 w0.127: v1(24.8,24.37) 25.61,25.18 25.61,28.74 24.86,29.49 22.15,29.49 v1(21.21,30.43) ; CN5.22 54.13,31.15 48.62,36.66 48.62,43.63 CN6.28
  BOTTOM w0.127: v1(36.17,28.05) 36.53,28.41 53,28.41 CN5.22
PB0: length 77.7
  TOP w0.127: K1.2 40.61,36.31 v1(40.83,36.09) ; U1.18 23.3,26.32 23.94,26.96 34.18,26.96 v1(35.63,28.41)
  GND2 w0.127: CN6.32 42.9,48.07 42.9,38.16 v1(40.83,36.09)
  BOTTOM w0.127: CN5.18 52.69,20.82 52.69,24.97 51.89,25.77 37.77,25.77 35.63,27.91 v1(35.63,28.41) 35.63,29.04 40.83,34.24 v1(40.83,36.09)
PB1: length 76.4
  TOP w0.127: v1(43.22,36.61) 43.15,36.68 K1.3 ; U1.19 22.9,26.47 23.76,27.33 34.06,27.33 35.13,28.4 v1(35.13,28.92)
  GND2 w0.127: v1(43.22,36.61) 43.22,47.92 49.26,53.96 CN6.31
  BOTTOM w0.127: CN5.19 55.53,23.32 55.53,30.38 52.79,33.12 51.78,33.12 48.29,36.61 v1(43.22,36.61) 40.68,36.61 40.34,36.27 40.34,34.13 v1(35.13,28.92)
PB2: length 66.7
  TOP w0.127: U1.20 22.5,26.57 23.62,27.69 33.78,27.69 v1(34.59,28.5) ; CN6.30 51.1,51.19 45.26,51.19 R12.1 38.07,44 K1.1 38.09,39.04 38.09,35.3 v1(34.59,31.8)
  GND2 w0.127: v1(34.59,28.5) v1(34.59,31.8)
  BOTTOM w0.127: CN6.20 38.59,24.5 v1(34.59,28.5)
PB3: length 69
  TOP w0.127: U1.21 22.1,26.72 23.39,28.01 33.44,28.01 38.01,32.58 v1(48.18,32.58) 48.18,25.11 CN6.19 ; R13.1 44.81,46.38 47.31,48.88 CN6.29
  GND2 w0.127: CN6.29 48.24,45.79 48.24,32.64 v1(48.18,32.58)
PB4: length 59.6
  TOP w0.127: U1.22 21.7,26.8 23.21,28.31 33.29,28.31 37.83,32.85 38.85,32.85 39.13,33.13 v1(44.63,33.13) ; v1(44.81,39.92) R14.1
  GND2 w0.127: v1(44.81,39.92) 44.81,33.31 v1(44.63,33.13) 44.89,32.87 44.89,17.58 45.59,16.88 CN6.17
PB5: length 67.4
  TOP w0.127: U1.23 21.3,25.94 v1(21.18,26.06) ; R15.1 39.31,43.77 v1(39.29,43.75)
  GND2 w0.127: v1(39.29,43.75) 35.63,43.75 35.19,43.31 35.19,35.1 33.72,33.63 v1(33.69,33.63)
  BOTTOM w0.127: CN6.18 50.01,20.74 50.01,23.4 49.24,24.17 38.29,24.17 34.13,28.33 34.13,33.19 v1(33.69,33.63) 33.4,33.92 27.95,33.92 25.52,31.49 25.52,28.47 23.11,26.06 v1(21.18,26.06)
PB6: length 79.2
  TOP w0.127: U1.26 19.68,23.44 v1(19.57,23.55) ; R6.2 20.4,38.07 v1(19.57,37.24)
  GND2 w0.127: v1(19.57,37.24) v1(19.57,23.55) 19.57,22.18 18.9,21.51 18.9,20.45 18.37,19.92 15.3,19.92 12.2,16.82 8.73,16.82 CN6.12
  BOTTOM w0.127: v1(19.57,23.55) 18.32,22.3 18.32,19.55 20.87,17 47.24,17 48.78,15.46 52.97,15.46 CN5.16
PB7: length 109.4
  TOP w0.127: D7.2 v1(35.91,36.17) ; v1(18.22,23.47) 18.65,23.04 U1.27 ; 12.49,51.08 SW2.1 14.81,51.1 C23.2 R16.2 v1(16.85,51.09)
  GND2 w0.127: v1(16.85,51.09) 18.17,51.09 18.77,50.49 v1(18.77,34.22) 18.77,24.02 v1(18.22,23.47)
  BOTTOM w0.127: CN5.15 52.79,13.1 50.66,13.1 47.08,16.68 20.81,16.68 17.99,19.5 17.99,22.66 18.22,22.89 v1(18.22,23.47) 12.72,23.47 CN6.11 ; v1(35.91,36.17) 33.96,34.22 v1(18.77,34.22)
PB8: length 112.7
  TOP w0.127: U1.28 17.89,22.64 17.64,22.89 16.4,22.89 v1(15.77,22.26) 15.77,26.09 18.36,28.68 33.21,28.68 37.65,33.12 38.52,33.12 39.05,33.65 45.13,33.65 45.69,33.09 48.31,33.09 48.66,32.74 48.66,27.23 50.11,25.78 52.81,25.78 CN5.20 ; CN6.1 8.67,47.05 7.63,46.01 5.39,46.01 3.59,44.21 v1(3.59,17.99) 3.59,14.04 CN5.14
  BOTTOM w0.127: v1(15.77,22.26) 15.77,19.68 14.08,17.99 v1(3.59,17.99)
PB9: length 92.2
  TOP w0.127: CN6.2 7.43,43.58 4.4,43.58 4.07,43.25 4.07,23.18 ; v1(18.82,22.16) 18.9,22.24 U1.29 ; CN5.13 4.07,16.1 4.07,23.18 ; 4.07,23.18 v1(4.08,23.19)
  GND2 w0.127: v1(18.82,22.16) 18.19,21.53 10.87,21.53 9.2,23.2 4.09,23.2 v1(4.08,23.19)
  BOTTOM w0.127: v1(18.82,22.16) 18.93,22.05 18.93,19.31 20.94,17.3 47.43,17.3 49,15.73 53.02,15.73 CN5.17
PB10: length 83.6
  TOP w0.127: v1(17.38,22.4) 18.19,21.59 19.02,21.59 19.27,21.84 U1.30
  GND2 w0.127: v1(16.07,39.37) 16.5,38.94 16.5,23.28 v1(17.38,22.4)
  BOTTOM w0.127: CN5.24 52.92,37.35 37.46,37.35 35.8,39.01 26.19,39.01 25.83,39.37 v1(16.07,39.37) 9.04,39.37 CN6.4 ; v1(17.38,22.4) 16.13,21.15 16.13,19.37 12.45,15.69 7.02,15.69 CN5.12
PB11: length 87.2
  TOP w0.127: U1.32 20.05,21.04 19.88,20.87 18.18,20.87 v1(16.68,22.37)
  GND2 w0.127: CN6.3 7.52,41.13 7.52,39.08 8.14,38.46 13.97,38.46 15.89,36.54 v1(15.89,36.53) 15.9,36.53 16.23,36.2 16.23,22.82 v1(16.68,22.37)
  BOTTOM w0.127: v1(16.68,22.37) 16.68,22.38 15.97,23.09 13,23.09 10.01,20.1 10.01,18.96 9.34,18.29 6.96,18.29 CN5.11 ; CN5.23 51.82,33.6 48.34,37.08 36.41,37.08 35.04,38.45 17.81,38.45 v1(15.89,36.53)
PB19: length 81.4
  TOP w0.127: U1.2 21.3,20.14 21.08,19.92 10.71,19.92 CN6.10 16.13,29.42 33,29.42 v1(37.7,34.12) 49.27,34.12 CN6.24 ; R2.2 36.24,40.57 v1(36.97,40.57)
  GND2 w0.127: CN6.24 51.33,34.46 55.42,30.37 55.42,28.18 54.24,27 CN5.21 ; v1(36.97,40.57) 37.7,39.84 v1(37.7,34.12)
PB20: length 70.4
  TOP w0.127: R1.1 36.21,41.57 v1(37.09,41.57) ; U1.1 18.09,20.44 16.84,21.69 15.67,21.69 15.29,22.07 v1(15.29,24.43) 15.29,26.05 18.31,29.07 33.14,29.07 37.68,33.61 v1(38.15,33.61)
  GND2 w0.127: CN6.9 8.74,24.43 v1(15.29,24.43) ; v1(37.09,41.57) 38.15,40.51 v1(38.15,33.61)
  BOTTOM w0.127: CN6.25 50.26,37.65 37.69,37.65 37.47,37.87 37.47,41.19 v1(37.09,41.57)
RST_N: length 107.4
  TOP w0.127: v1(5.12,51.1) SW1.1 6.65,51.13 R9.2 C20.2 ; C32.1 v1(36.13,38.04) ; C33.1 25.76,39.08 v1(25.58,38.9) ; U1.4 22.1,20.16 21.28,19.34 16.32,19.34 8.78,11.8 CN6.14
  GND2 w0.127: v1(15.47,38.92) 15.47,42.44 14.39,43.52 7.15,43.52 CN5.3
  BOTTOM w0.127: v1(36.13,38.04) 35.42,38.75 25.73,38.75 v1(25.58,38.9) 25.56,38.92 v1(15.47,38.92) ; v1(5.12,51.1) 4.97,51.1 4.36,50.49 4.36,43.75 CN5.3 3.04,39.41 3.04,11.95 4.81,10.18 7.05,10.18 CN6.14
WAKEUP: length 15.7
  TOP w0.127: U1.3 21.7,20.15 21.18,19.63 13.96,19.63 CN6.13
XTAL_IN: length 6.7
  TOP w0.127: U1.6 22.9,20.14 21.53,18.77 19.92,18.77 19.71,18.56 U2.3 20.26,17.09 21.05,17.09 C3.1
XTAL_OUT: length 9.3
  TOP w0.127: C6.2 16.04,15.94 U2.1 17.54,15.94 18.67,17.07 18.67,18.37 19.37,19.07 21.42,19.07 22.5,20.15 U1.5
N16680375: length 2.1
  TOP w0.254: R17.1 31.37,34.45 D1.1
N16684582: length 1.9
  TOP w0.203: R4.2 30.08,36.45 U6.13
N16684586: length 2.4
  TOP w0.203: U6.12 28.38,39.07 R6.1
N16727459: length 2.6
  TOP w0.127: R18.1 40.61,27.75 K1.5
N16727471: length 6.2
  TOP w0.127: LED1.3 40.59,20.94 R18.2
N16730113: length 2.7
  TOP w0.127: K1.4 43.15,27.74 R19.1
N16730133: length 2.7
  TOP w0.127: K1.6 38.07,27.74 R20.1
N16730206: length 6.5
  TOP w0.127: R20.2 38.06,21.59 LED1.4
N16730210: length 6.2
  TOP w0.127: R19.2 43.14,20.98 LED1.1
N16735482: length 2.1
  TOP w0.203: C33.2 27.88,39.57 U6.11
N16736464: length 2
  TOP w0.203: C32.2 35.3,39.07 U6.19
N16746225: length 3.1
  TOP w0.293: R5.2 R7.2 D2.1 23.7,13.25 C11.2 23.7,14.21 L2.2
N16746337: length 2.2
  TOP w0.127: C2.1 19.2,24.69 20.05,23.84 U1.25
N16746437: length 3
  TOP w0.127: 23.7,18.17 C31.2
  TOP w0.293: 23.7,18.18 D3.1 23.69,17.17 C14.2 23.7,16.23 L2.1
N16750371: length 3.4
  TOP w0.293: J3.1 28.09,11.13 R7.1
N16770024: length 11.3
  TOP w0.127: R12.2 50.25,50.59 50.73,50.11 52.14,50.11 52.87,49.38 52.87,47.56 CN5.28
N16770030: length 8.9
  TOP w0.127: CN5.27 52.89,45 46.09,45 R13.2
N16770036: length 9.4
  TOP w0.127: R15.2 49.27,43.77 50.55,42.49 52.86,42.49 CN5.26
N16770042: length 9.8
  TOP w0.127: R14.2 48.23,39.93 52.88,39.93 CN5.25
N16796539: length 1.3
  TOP w0.127: 23.7,19.2 23.7,19.19 C31.1
  TOP w0.2: 23.7,19.2 U1.8
N16801010: length 2.5
  TOP w0.203: R1.2 33.69,40.07 U6.21
N16801016: length 2.3
  TOP w0.203: R2.1 34.22,39.57 U6.20
N16801188: length 2.5
  TOP w0.254: C36.1 30.08,42.68 U6.6
N16801254: length 2.1
  TOP w0.254: R23.2 27.9,40.57 U6.9
N16808784: length 1.9
  TOP w0.254: U6.8 R24.1
N166846780: length 1.5
  TOP w0.203: R4.1 32.19,36.44 D7.1

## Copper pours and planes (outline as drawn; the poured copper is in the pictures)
+5V on TOP: 30.47,48.04 29.06,48.04 28.49,48.61 27.89,48.61 27.71,48.44 27.71,47.55 27.71,47.55 27.71,47.35 27.85,47.21 30.38,47.21 30.65,47.48 30.65,47.86
VCC_33 on TOP: 16.41,38.5 18.48,38.5 19.02,37.96 19.02,36.85 22.04,33.83 23.84,33.83 23.95,33.72 23.95,32.25 23.53,31.83 22.22,31.83 17.01,37.04 16.6,37.04 16.17,37.47 16.17,38.26
VCC_33 on TOP: 23.75,33.84 26.1,33.84 26.68,33.26 30.83,33.26 31.01,33.08 31.01,32.44 30.08,31.51 30.06,31.51 30.06,31.11 29.78,30.83 25.9,30.83 23.75,32.98
Net_58 on TOP (solid shape): 19.45,7.09 20.65,7.09 20.65,7.1 20.65,7.84 21.65,7.84 21.65,5.8 13.65,5.8 13.65,3.13 19.45,3.13 19.45,3.94 18.45,3.94 18.45,5.15 21.65,5.15 21.65,3.94 20.65,3.94 20.65,2.13 37.25,2.13 37.25,0.92 11.47,0.92 11.47,7.09 18.45,7.09 18.45,7.84 19.45,7.84

Small or netless copper shapes (teardrops, artwork), in the pictures only: 1 on TOP, 1 on BOTTOM, 1 on GND1, 1 on GND2

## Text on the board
Ref Des/Silkscreen Bottom: NC | 3V3 | GND | +5V | RST | PA1 | PB11 | PB8 | PB10 | PA4 | PB9 | PB7 | PB6 | PA7 | PB20 | PB19 | WAKEUP | PB0 | PB1 | PB3 | PB5 | PB2 | PB4
Ref Des/Silkscreen Top: U1 | TYPE-C | B- | G- | R- | WWW.WINNERMICRO.COM | W800_ARDUINO_V4.0 | SCL | SDA | GND | 12 | 10 | 11 | 13 | +5V | 3V3 | NC | PA4 | RST | PA1 | PB10 | VIN | PB11 | PB9 | PB8 | CN5-2 | CN5-1 | CN6-2 | CN6-1 | DO | DI | LCK | MCK | BCK | TX1 | CTS | WAK | RX1 | RTS | TX0 | RX0 | PWM1 | PWM3 | PWM4 | PWM2 | PWM0 | CS | CLK | DAT | CN6-4 | CN6-3 | CN5-3 | CN5-4 | 8 | 9 | 7 | 6 | 4 | 5 | 3 | 0 | 1 | 2 | USER | UART1 | I2S | BOOT | SPI | SWD
User.8: FIGURE | FINISHED_SIZE | 0.254 | 0.6 | 0.8999 | 0.9 | 1.1 | 2.3 | 1.4x0.6 | 1.7x0.6 | DRILL CHART: TOP to BOTTOM | ALL UNITS ARE IN MILLIMETERS | ROTATION | - | 90.000 | PLATED | NON-PLATED | QTY | 471 | 46 | 4 | 16 | 2 | 45
